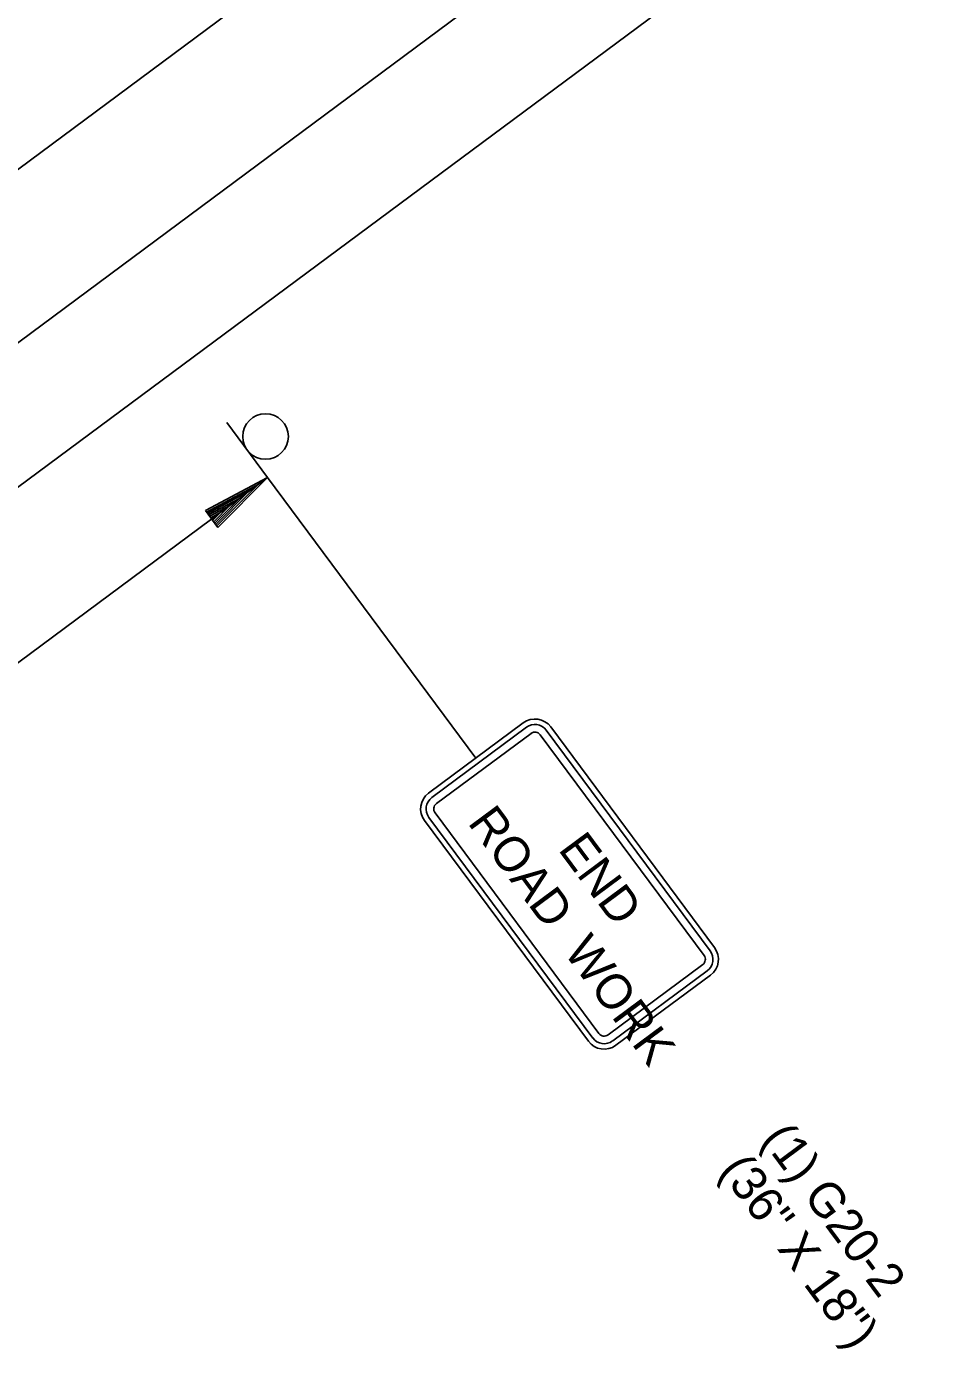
# Model space of a CAD drawing. Extents: x 998982 to 1000626, y 1875366 to 1876934.
# Drawn here: x 1000080 to 1000238.9, y 1876021.6 to 1876250.2 of the extents above; entities that cross this region are included whole.
import ezdxf

# ---------------------------------------------------------------- set-up
doc = ezdxf.new("R2010")
doc.units = 0
for name, color, linetype in [('P_TC_Signs_Temporary', 7, 'Continuous'), ('R_Border Prem', 7, 'Continuous'), ('R_Draft', 7, 'Continuous'), ('STAMP', 7, 'Continuous')]:
    doc.layers.add(name, color=color, linetype=linetype)

msp = doc.modelspace()

# ---------------------------------------------------------------- linework, layer by layer
at = {"layer": 'P_TC_Signs_Temporary'}
for p, q in [((1000165.31, 1876130.48), (1000149.05, 1876118.41)), ((1000165.87, 1876129.73), (1000149.61, 1876117.66)), ((1000166.65, 1876128.68), (1000150.39, 1876116.61)), ((1000196.39, 1876090.51), (1000168.23, 1876128.45)), ((1000197.45, 1876091.29), (1000169.28, 1876129.23)), ((1000198.2, 1876091.85), (1000170.03, 1876129.79)), ((1000150.16, 1876115.03), (1000178.33, 1876077.1)), ((1000148.35, 1876113.69), (1000176.52, 1876075.76)), ((1000149.11, 1876114.25), (1000177.28, 1876076.31)), ((1000179.9, 1876076.86), (1000196.16, 1876088.94)), ((1000180.69, 1876075.81), (1000196.94, 1876087.88)), ((1000181.24, 1876075.06), (1000197.5, 1876087.13))]:
    msp.add_line(p, q, dxfattribs=at)
for centre, radius, start, end in [((1000167.32, 1876127.78), 3.38, 36.5953, 126.5953), ((1000167.32, 1876127.78), 2.44, 36.5953, 126.5953), ((1000167.32, 1876127.78), 1.13, 36.5953, 126.5953), ((1000151.06, 1876115.7), 3.38, 126.5953, 216.5953), ((1000151.06, 1876115.7), 2.44, 126.5953, 216.5953), ((1000151.06, 1876115.7), 1.13, 126.5953, 216.5953), ((1000195.49, 1876089.84), 3.38, 306.5953, 36.5953), ((1000195.49, 1876089.84), 1.13, 306.5953, 36.5953), ((1000195.49, 1876089.84), 2.44, 306.5953, 36.5953), ((1000179.23, 1876077.77), 2.44, 216.5953, 306.5953), ((1000179.23, 1876077.77), 1.13, 216.5953, 306.5953), ((1000179.23, 1876077.77), 3.38, 216.5953, 306.5953)]:
    msp.add_arc(centre, radius, start, end, dxfattribs=at)
at = {"layer": 'R_Draft'}
for p, q in [((1000401.91, 1876465.85), (999851.04, 1876056.81)), ((1000416.18, 1876446.63), (999865.31, 1876037.59)), ((1000428.07, 1876430.61), (999877.2, 1876021.57)), ((999960.81, 1876053.44), (1000121.38, 1876172.68)), ((1000110.7, 1876166.98), (1000121.38, 1876172.68)), ((1000112.84, 1876164.1), (1000121.38, 1876172.68)), ((1000121.37, 1876172.67), (1000157.18, 1876124.45)), ((1000110.88, 1876166.74), (1000119.78, 1876171.48)), ((1000111.06, 1876166.5), (1000118.12, 1876170.26)), ((1000112.48, 1876164.58), (1000118.12, 1876170.26)), ((1000112.66, 1876164.34), (1000119.78, 1876171.48)), ((1000111.24, 1876166.26), (1000116.53, 1876169.07)), ((1000111.43, 1876166.01), (1000114.89, 1876167.86)), ((1000112.12, 1876165.07), (1000114.89, 1876167.86)), ((1000112.3, 1876164.82), (1000116.53, 1876169.07)), ((1000110.7, 1876166.98), (1000112.84, 1876164.1)), ((1000111.6, 1876165.77), (1000113.29, 1876166.67)), ((1000111.94, 1876165.32), (1000113.29, 1876166.67))]:
    msp.add_line(p, q, dxfattribs=at)
at = {"layer": 'STAMP'}
msp.add_line((1000121.37, 1876172.67), (1000114.37, 1876182.11), dxfattribs=at)
msp.add_circle((1000121.02, 1876179.73), 3.92, dxfattribs=at)

# ---------------------------------------------------------------- texts
at = {"layer": 'P_TC_Signs_Temporary'}
for s, p in [('ROAD  WORK', (1000155.65, 1876113.3)), ('END', (1000171.19, 1876108.73))]:
    msp.add_text(s, height=6, rotation=306.5953, dxfattribs=at).set_placement(p)
at = {"layer": 'R_Border Prem'}
for s, p in [('(1) G20-2', (1000206.12, 1876058.87)), ('(36" X 18")', (1000198.89, 1876053.51))]:
    msp.add_text(s, height=6, rotation=306.5953, dxfattribs=at).set_placement(p)

doc.saveas('drawing.dxf')
